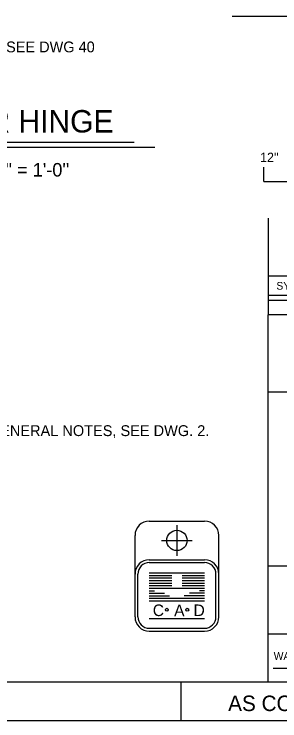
# Model space of a CAD drawing. Extents: x -0.2 to 13.5, y -0.2 to 9.5.
# Drawn here: x 9.907 to 11.051, y 0 to 3.047 of the extents above; entities that cross this region are included whole.
import ezdxf

# ---------------------------------------------------------------- set-up
doc = ezdxf.new("R2010")
doc.units = 0
for name, color, linetype in [('Level 1', 7, 'Continuous'), ('Level 2', 7, 'Continuous'), ('Level 3', 7, 'Continuous')]:
    doc.layers.add(name, color=color, linetype=linetype)

msp = doc.modelspace()

# ---------------------------------------------------------------- linework, layer by layer
at = {"layer": 'Level 1'}
for p, q in [((10.9821, 2.3251), (10.9821, 2.3876)), ((10.9821, 2.3251), (12.9821, 2.3251)), ((11, 2.1667), (11, 1.75)), ((13.1667, 1.9167), (11, 1.9167)), ((13.1667, 1.8333), (11, 1.8333)), ((13.1667, 1.8125), (11, 1.8125)), ((11, 0.1667), (11, 1.75)), ((13.1667, 1.75), (11, 1.75)), ((13.1667, 1.4167), (11, 1.4167)), ((10.4887, 0.8613), (10.7265, 0.8613)), ((10.6076, 0.8438), (10.6076, 0.712)), ((10.4272, 0.4483), (10.4272, 0.7998)), ((10.7881, 0.4483), (10.7881, 0.7998)), ((10.5417, 0.7779), (10.6735, 0.7779)), ((10.4887, 0.6944), (10.7265, 0.6944)), ((10.4887, 0.6821), (10.7265, 0.6821)), ((13.1667, 0.6667), (11, 0.6667)), ((10.4395, 0.4483), (10.4395, 0.6329)), ((10.4887, 0.6382), (10.7265, 0.6382)), ((10.4887, 0.6272), (10.5857, 0.6272)), ((10.4887, 0.6162), (10.5857, 0.6162)), ((10.6296, 0.6272), (10.7265, 0.6272)), ((10.6296, 0.6162), (10.7265, 0.6162)), ((10.7757, 0.4483), (10.7757, 0.6329)), ((10.4887, 0.6052), (10.5857, 0.6052)), ((10.4887, 0.5942), (10.5857, 0.5942)), ((10.4887, 0.5832), (10.5857, 0.5832)), ((10.6296, 0.6052), (10.7265, 0.6052)), ((10.6296, 0.5942), (10.7265, 0.5942)), ((10.6296, 0.5832), (10.7265, 0.5832)), ((10.4887, 0.5722), (10.7265, 0.5722)), ((10.4887, 0.5613), (10.5107, 0.5613)), ((10.4887, 0.5503), (10.5535, 0.5503)), ((10.7265, 0.5503), (10.6617, 0.5503)), ((10.7265, 0.5613), (10.7045, 0.5613)), ((10.4887, 0.5393), (10.576, 0.5393)), ((10.4887, 0.5283), (10.7265, 0.5283)), ((10.7265, 0.5393), (10.6392, 0.5393)), ((10.4887, 0.5173), (10.7265, 0.5173)), ((10.4887, 0.441), (10.7269, 0.441)), ((10.4887, 0.3991), (10.7265, 0.3991)), ((10.4887, 0.3869), (10.7265, 0.3869)), ((11, 0.375), (11.75, 0.375)), ((11.0224, 0.2278), (11.7234, 0.2278)), ((10.625, 0.1667), (10.625, 0))]:
    msp.add_line(p, q, dxfattribs=at)
for points in [[(0, 9.3333), (13.3333, 9.3333), (13.3333, 0), (0, 0)], [(0.5, 9.1667), (13.1667, 9.1667), (13.1667, 0.1667), (0.5, 0.1667)]]:
    msp.add_lwpolyline(points, close=True, dxfattribs=at)
for centre, radius in [((10.6076, 0.7778), 0.0439), ((10.564, 0.4792), 0.00615), ((10.6521, 0.4792), 0.00615)]:
    msp.add_circle(centre, radius, dxfattribs=at)
for centre, radius, start, end in [((10.4887, 0.7998), 0.0615, 90, 180), ((10.7265, 0.7998), 0.0615, 0, 90), ((10.4887, 0.6329), 0.0615, 90, 180), ((10.4887, 0.6329), 0.0492, 90, 180), ((10.7265, 0.6329), 0.0615, 0, 90), ((10.7265, 0.6329), 0.0492, 0, 90), ((10.4887, 0.4484), 0.0615, 180, 270), ((10.4887, 0.4484), 0.0492, 180, 270), ((10.7265, 0.4484), 0.0615, 270, 360), ((10.7265, 0.4484), 0.0492, 270, 360)]:
    msp.add_arc(centre, radius, start, end, dxfattribs=at)
at = {"layer": 'Level 2'}
msp.add_line((11, 1.75), (11, 1.75), dxfattribs=at)
at = {"layer": 'Level 3'}
for p, q in [((10.845, 3.0387), (11.5798, 3.0387)), ((9.3009, 2.4734), (10.5128, 2.4734)), ((9.3729, 2.4943), (10.4232, 2.4943))]:
    msp.add_line(p, q, dxfattribs=at)

# ---------------------------------------------------------------- texts
at = {"layer": 'Level 1'}
for s, height, p in [("12''", 0.04, (10.9658, 2.4096)), ('SYMBOL', 0.03321, (11.0358, 1.859)), ('C', 0.05, (10.5037, 0.4517)), ('A', 0.05, (10.5956, 0.4513)), ('D', 0.05, (10.6792, 0.4517))]:
    msp.add_text(s, height=height, dxfattribs=at).set_placement(p)
at = {"layer": 'Level 2'}
for s, height, p in [('WALTER O. BAUMY JR., P.E.', 0.033208, (11.0243, 0.2631)), ('AS CONSTRUCTED', 0.066792, (10.8281, 0.0422))]:
    msp.add_text(s, height=height, dxfattribs=at).set_placement(p)
at = {"layer": 'Level 3'}
for s, height, p in [('DENOTES MARK NUMBERS, SEE DWG 40', 0.046667, (9.0089, 2.8822)), ('LOWER HINGE', 0.096667, (9.4153, 2.5366)), ("SCALE: 3'' = 1'-0''", 0.058333, (9.5257, 2.3467)), ('FOR GENERAL NOTES, SEE DWG. 2.', 0.046792, (9.6485, 1.2278))]:
    msp.add_text(s, height=height, dxfattribs=at).set_placement(p)

doc.saveas('drawing.dxf')
